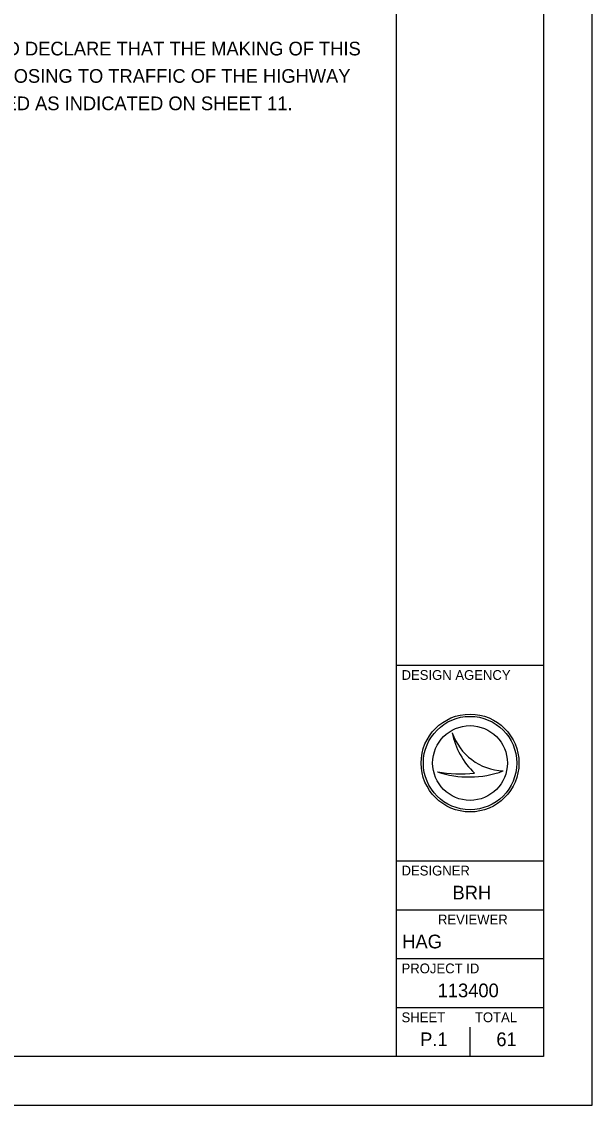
# Model space of a CAD drawing. Extents: x 0 to 34, y 0 to 22.
# Drawn here: x 28.17 to 34, y 0 to 11.08 of the extents above; entities that cross this region are included whole.
import ezdxf

# ---------------------------------------------------------------- set-up
doc = ezdxf.new("R2010")
doc.units = 0
for name, color, linetype in [('SH_Border', 7, 'Continuous'), ('SH_Cut_Line', 7, 'Continuous'), ('SH_Data', 7, 'Continuous'), ('SH_Text', 7, 'Continuous')]:
    doc.layers.add(name, color=color, linetype=linetype)

msp = doc.modelspace()

# ---------------------------------------------------------------- linework, layer by layer
at = {"layer": 'SH_Border'}
for p, q in [((32, 0.5), (32, 21.5)), ((32, 4.5), (33.5, 4.5)), ((32, 2.5), (33.5, 2.5)), ((32, 2), (33.5, 2)), ((32, 1.5), (33.5, 1.5)), ((32, 1), (33.5, 1))]:
    msp.add_line(p, q, dxfattribs=at)
msp.add_lwpolyline([(1.5, 21.5), (33.5, 21.5), (33.5, 0.5), (1.5, 0.5)], close=True, dxfattribs=at)
at = {"layer": 'SH_Cut_Line'}
msp.add_lwpolyline([(0, 0), (34, 0), (34, 22), (0, 22)], close=True, dxfattribs=at)
at = {"layer": 'SH_Data'}
for p, q in [((32.567, 3.81), (32.567, 3.81)), ((32.75, 3.5), (32.75, 3.5)), ((32.417, 3.41), (32.417, 3.41)), ((33.087, 3.419), (33.087, 3.419)), ((32.75, 0.5), (32.75, 0.8)), ((32.375, 0.675), (32.375, 0.675))]:
    msp.add_line(p, q, dxfattribs=at)
for radius in [0.5, 0.477, 0.477, 0.382]:
    msp.add_circle((32.75, 3.5), radius, dxfattribs=at)
for centre, radius, start, end in [((33.116, 3.998), 0.58, 198.9257, 198.9319), ((33.347, 3.97), 0.796, 191.6379, 191.6421), ((33.116, 3.998), 0.58, 198.9319, 267.1657), ((33.347, 3.97), 0.796, 191.6421, 226.0947), ((32.739, 4.37), 1.013, 251.4576, 290.0832), ((32.648, 4.654), 1.266, 259.4964, 259.4995), ((32.739, 4.37), 1.013, 251.4527, 251.4576), ((32.648, 4.654), 1.266, 259.4995, 276.6672)]:
    msp.add_arc(centre, radius, start, end, dxfattribs=at)

# ---------------------------------------------------------------- texts
for s, height, p in [('DESIGN AGENCY', 0.1, (32.05, 4.35)), ('DESIGNER', 0.1, (32.05, 2.35)), ('BRH', 0.14, (32.571, 2.105)), ('REVIEWER', 0.1, (32.422, 1.85)), ('HAG', 0.14, (32.057, 1.605)), ('PROJECT ID', 0.1, (32.05, 1.35)), ('113400', 0.14, (32.419, 1.105)), ('SHEET', 0.1, (32.05, 0.85)), ('TOTAL', 0.1, (32.8, 0.85)), ('P.1', 0.14, (32.24, 0.605)), ('61', 0.14, (33.019, 0.605))]:
    msp.add_text(s, height=height, dxfattribs=at).set_placement(p)
at = {"layer": 'SH_Text'}
for s, p in [('I HEREBY APPROVE THESE PLANS AND DECLARE THAT THE MAKING OF THIS', (24.528, 10.735)), ('IMPROVEMENT WILL REQUIRE  THE CLOSING TO TRAFFIC OF THE HIGHWAY', (24.528, 10.455)), ('AND THAT DETOURS WILL BE PROVIDED AS INDICATED ON SHEET 11.', (24.528, 10.175))]:
    msp.add_text(s, height=0.14, dxfattribs=at).set_placement(p)

doc.saveas('drawing.dxf')
